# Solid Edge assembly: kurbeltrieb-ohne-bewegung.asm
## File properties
Author: helmut
Template: Normal.asm
Last saved by: helmut
Revision: 2
Application: Solid Edge
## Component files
Grundkoerper.par
Schieber.par
Drehscheibe.par
Hebel.par
Stufenbolzen.par
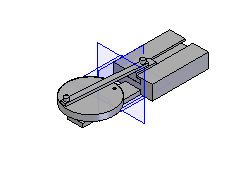
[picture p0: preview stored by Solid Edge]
